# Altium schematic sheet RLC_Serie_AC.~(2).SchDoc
size A4
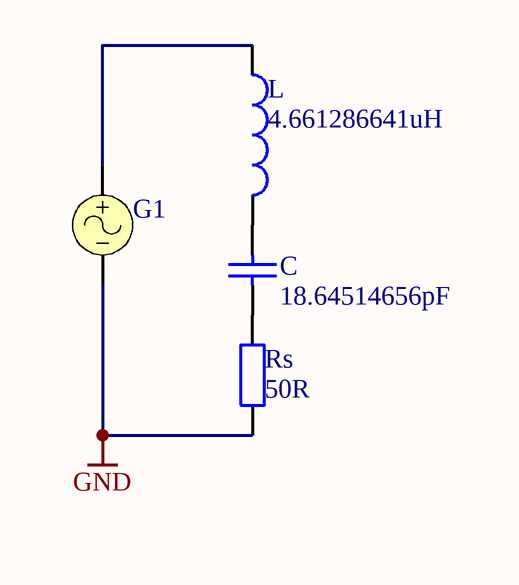
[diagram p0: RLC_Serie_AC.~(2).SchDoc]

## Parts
C  value 18.64514656pF  [RAD-0.3]  (hidden comment: Cap)
G1  VSIN  (value not drawn)
L  value 4.661286641uH  [0402-A]  (hidden comment: Inductor)
Rs  value 50R  [AXIAL-0.4]  (hidden comment: Res2)

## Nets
GND: G1.2 Rs.1
NetC_1: C.1 Rs.2
NetC_2: C.2 L.2
NetG1_1: G1.1 L.1

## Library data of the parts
C = Cap: Capacitor
G1 = VSIN: Sinusoidal Voltage Source; Note: PCB Footprint - Not required
L = Inductor: Code_IEC: 1005
Rs = Res2: Resistor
